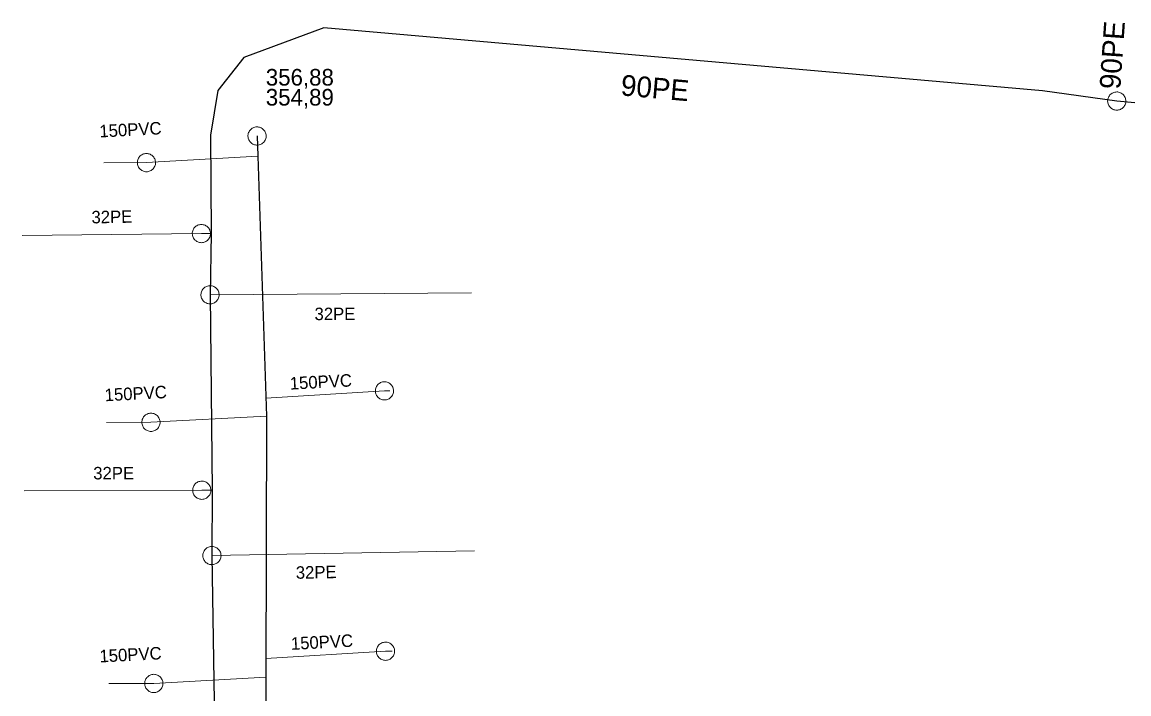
# Model space of a CAD drawing. Extents: x -741806 to -738704, y -1059275 to -1055387.
# Drawn here: x -740777.3 to -740724.1, y -1057612.9 to -1057580.6 of the extents above; entities that cross this region are included whole.
import ezdxf

# ---------------------------------------------------------------- set-up
doc = ezdxf.new("R2010")
doc.units = 0
doc.header["$LTSCALE"] = 0.4
for name, color, linetype, lineweight in [('2', 7, 'Continuous', 25), ('21', 7, 'Continuous', 13), ('3', 7, 'Continuous', 13), ('46', 7, 'Continuous', 13), ('51', 7, 'Continuous', 13), ('52', 7, 'Continuous', 25), ('56', 7, 'Continuous', 13)]:
    doc.layers.add(name, color=color, linetype=linetype, lineweight=lineweight)
for name, color, linetype in [('53', 7, 'Continuous'), ('54', 7, 'Continuous'), ('55', 7, 'Continuous')]:
    doc.layers.add(name, color=color, linetype=linetype)

msp = doc.modelspace()

# ---------------------------------------------------------------- linework, layer by layer
at = {"layer": '2'}
msp.add_lwpolyline([(-740766.015, -1057586.107), (-740765.982, -1057587.074), (-740765.563, -1057599.558), (-740765.594, -1057612.098), (-740765.511, -1057624.514), (-740765.321, -1057634.66)], dxfattribs=at)
at = {"layer": '21'}
for p, q in [((-740768.276, -1057593.736), (-740755.704, -1057593.635)), ((-740768.186, -1057606.262), (-740755.563, -1057606.027))]:
    msp.add_line(p, q, dxfattribs=at)
for points in [[(-740768.221, -1057590.793), (-740768.692, -1057590.797), (-740777.307, -1057590.884)], [(-740768.169, -1057603.12), (-740768.673, -1057603.125), (-740777.206, -1057603.157)]]:
    msp.add_lwpolyline(points, dxfattribs=at)
at = {"layer": '3'}
msp.add_lwpolyline([(-740766, -1057586.544), (-740765.955, -1057586.54), (-740765.911, -1057586.531), (-740765.866, -1057586.518), (-740765.825, -1057586.5), (-740765.784, -1057586.478), (-740765.746, -1057586.452), (-740765.712, -1057586.422), (-740765.68, -1057586.388), (-740765.654, -1057586.352), (-740765.63, -1057586.313), (-740765.61, -1057586.271), (-740765.595, -1057586.228), (-740765.585, -1057586.183), (-740765.579, -1057586.138), (-740765.578, -1057586.092), (-740765.582, -1057586.046), (-740765.591, -1057586.001), (-740765.604, -1057585.958), (-740765.622, -1057585.915), (-740765.645, -1057585.875), (-740765.671, -1057585.838), (-740765.7, -1057585.804), (-740765.734, -1057585.772), (-740765.77, -1057585.744), (-740765.81, -1057585.72), (-740765.851, -1057585.702), (-740765.894, -1057585.686), (-740765.939, -1057585.676), (-740765.985, -1057585.67), (-740766.031, -1057585.67), (-740766.076, -1057585.673), (-740766.12, -1057585.682), (-740766.165, -1057585.695), (-740766.207, -1057585.714), (-740766.247, -1057585.735), (-740766.285, -1057585.761), (-740766.319, -1057585.792), (-740766.351, -1057585.826), (-740766.377, -1057585.862), (-740766.401, -1057585.9), (-740766.421, -1057585.942), (-740766.436, -1057585.986), (-740766.447, -1057586.03), (-740766.452, -1057586.075), (-740766.453, -1057586.121), (-740766.449, -1057586.167), (-740766.441, -1057586.212), (-740766.427, -1057586.255), (-740766.409, -1057586.298), (-740766.386, -1057586.338), (-740766.36, -1057586.375), (-740766.331, -1057586.41), (-740766.297, -1057586.441), (-740766.261, -1057586.469), (-740766.221, -1057586.493), (-740766.18, -1057586.512), (-740766.137, -1057586.527), (-740766.092, -1057586.537), (-740766.046, -1057586.543), (-740766.001, -1057586.544)], dxfattribs=at)
at = {"layer": '46'}
for points in [[(-740770.895, -1057587.383), (-740770.898, -1057587.338), (-740770.905, -1057587.293), (-740770.917, -1057587.248), (-740770.933, -1057587.206), (-740770.955, -1057587.165), (-740770.98, -1057587.126), (-740771.009, -1057587.092), (-740771.041, -1057587.059), (-740771.077, -1057587.031), (-740771.115, -1057587.006), (-740771.156, -1057586.985), (-740771.199, -1057586.968), (-740771.243, -1057586.958), (-740771.288, -1057586.95), (-740771.334, -1057586.948), (-740771.38, -1057586.95), (-740771.425, -1057586.958), (-740771.469, -1057586.97), (-740771.512, -1057586.987), (-740771.553, -1057587.008), (-740771.591, -1057587.033), (-740771.626, -1057587.061), (-740771.659, -1057587.094), (-740771.688, -1057587.13), (-740771.712, -1057587.169), (-740771.732, -1057587.21), (-740771.749, -1057587.252), (-740771.761, -1057587.297), (-740771.768, -1057587.342), (-740771.769, -1057587.388), (-740771.767, -1057587.433), (-740771.76, -1057587.478), (-740771.748, -1057587.523), (-740771.731, -1057587.566), (-740771.71, -1057587.606), (-740771.685, -1057587.645), (-740771.656, -1057587.679), (-740771.623, -1057587.712), (-740771.588, -1057587.74), (-740771.55, -1057587.765), (-740771.509, -1057587.786), (-740771.466, -1057587.803), (-740771.422, -1057587.814), (-740771.377, -1057587.821), (-740771.331, -1057587.823), (-740771.285, -1057587.821), (-740771.24, -1057587.814), (-740771.196, -1057587.801), (-740771.153, -1057587.784), (-740771.112, -1057587.763), (-740771.074, -1057587.738), (-740771.038, -1057587.71), (-740771.006, -1057587.677), (-740770.977, -1057587.641), (-740770.953, -1057587.602), (-740770.932, -1057587.561), (-740770.916, -1057587.519), (-740770.904, -1057587.474), (-740770.897, -1057587.429), (-740770.895, -1057587.384)], [(-740760.329, -1057598.355), (-740760.326, -1057598.4), (-740760.318, -1057598.445), (-740760.306, -1057598.49), (-740760.289, -1057598.532), (-740760.268, -1057598.572), (-740760.243, -1057598.611), (-740760.213, -1057598.646), (-740760.181, -1057598.678), (-740760.144, -1057598.706), (-740760.106, -1057598.73), (-740760.065, -1057598.751), (-740760.022, -1057598.768), (-740759.978, -1057598.778), (-740759.933, -1057598.785), (-740759.886, -1057598.787), (-740759.841, -1057598.784), (-740759.796, -1057598.776), (-740759.752, -1057598.764), (-740759.709, -1057598.747), (-740759.668, -1057598.725), (-740759.63, -1057598.7), (-740759.596, -1057598.672), (-740759.563, -1057598.638), (-740759.535, -1057598.603), (-740759.51, -1057598.564), (-740759.49, -1057598.522), (-740759.474, -1057598.48), (-740759.462, -1057598.435), (-740759.456, -1057598.39), (-740759.455, -1057598.344), (-740759.457, -1057598.299), (-740759.465, -1057598.254), (-740759.477, -1057598.209), (-740759.495, -1057598.166), (-740759.515, -1057598.127), (-740759.54, -1057598.088), (-740759.57, -1057598.053), (-740759.603, -1057598.021), (-740759.639, -1057597.993), (-740759.677, -1057597.969), (-740759.718, -1057597.948), (-740759.761, -1057597.931), (-740759.805, -1057597.92), (-740759.85, -1057597.914), (-740759.897, -1057597.912), (-740759.942, -1057597.915), (-740759.987, -1057597.922), (-740760.031, -1057597.935), (-740760.074, -1057597.952), (-740760.115, -1057597.974), (-740760.153, -1057597.999), (-740760.188, -1057598.027), (-740760.22, -1057598.061), (-740760.248, -1057598.096), (-740760.273, -1057598.135), (-740760.294, -1057598.177), (-740760.309, -1057598.219), (-740760.321, -1057598.264), (-740760.327, -1057598.309), (-740760.329, -1057598.354)], [(-740770.676, -1057599.858), (-740770.679, -1057599.813), (-740770.686, -1057599.768), (-740770.698, -1057599.723), (-740770.714, -1057599.681), (-740770.736, -1057599.64), (-740770.761, -1057599.601), (-740770.79, -1057599.566), (-740770.822, -1057599.533), (-740770.858, -1057599.506), (-740770.896, -1057599.481), (-740770.938, -1057599.46), (-740770.981, -1057599.443), (-740771.025, -1057599.433), (-740771.07, -1057599.425), (-740771.116, -1057599.423), (-740771.162, -1057599.425), (-740771.207, -1057599.433), (-740771.251, -1057599.445), (-740771.294, -1057599.462), (-740771.334, -1057599.483), (-740771.372, -1057599.508), (-740771.407, -1057599.537), (-740771.44, -1057599.57), (-740771.469, -1057599.605), (-740771.494, -1057599.644), (-740771.513, -1057599.685), (-740771.53, -1057599.727), (-740771.542, -1057599.772), (-740771.549, -1057599.817), (-740771.55, -1057599.863), (-740771.548, -1057599.908), (-740771.541, -1057599.953), (-740771.529, -1057599.998), (-740771.512, -1057600.041), (-740771.491, -1057600.081), (-740771.466, -1057600.12), (-740771.437, -1057600.155), (-740771.404, -1057600.188), (-740771.369, -1057600.215), (-740771.331, -1057600.24), (-740771.289, -1057600.261), (-740771.246, -1057600.278), (-740771.202, -1057600.289), (-740771.157, -1057600.296), (-740771.111, -1057600.298), (-740771.065, -1057600.296), (-740771.02, -1057600.289), (-740770.976, -1057600.276), (-740770.933, -1057600.259), (-740770.893, -1057600.238), (-740770.855, -1057600.213), (-740770.819, -1057600.184), (-740770.787, -1057600.151), (-740770.758, -1057600.116), (-740770.733, -1057600.077), (-740770.713, -1057600.036), (-740770.697, -1057599.994), (-740770.685, -1057599.949), (-740770.678, -1057599.904), (-740770.676, -1057599.859)], [(-740760.281, -1057610.862), (-740760.278, -1057610.907), (-740760.271, -1057610.952), (-740760.258, -1057610.997), (-740760.242, -1057611.039), (-740760.22, -1057611.08), (-740760.195, -1057611.118), (-740760.166, -1057611.153), (-740760.133, -1057611.186), (-740760.097, -1057611.213), (-740760.059, -1057611.238), (-740760.018, -1057611.259), (-740759.975, -1057611.275), (-740759.931, -1057611.286), (-740759.885, -1057611.293), (-740759.839, -1057611.295), (-740759.793, -1057611.293), (-740759.749, -1057611.284), (-740759.705, -1057611.273), (-740759.662, -1057611.255), (-740759.621, -1057611.234), (-740759.583, -1057611.209), (-740759.548, -1057611.18), (-740759.516, -1057611.147), (-740759.487, -1057611.112), (-740759.462, -1057611.072), (-740759.443, -1057611.031), (-740759.426, -1057610.989), (-740759.415, -1057610.944), (-740759.408, -1057610.899), (-740759.407, -1057610.853), (-740759.409, -1057610.808), (-740759.416, -1057610.763), (-740759.429, -1057610.718), (-740759.446, -1057610.675), (-740759.467, -1057610.635), (-740759.492, -1057610.597), (-740759.521, -1057610.562), (-740759.555, -1057610.529), (-740759.59, -1057610.502), (-740759.628, -1057610.477), (-740759.669, -1057610.456), (-740759.712, -1057610.44), (-740759.757, -1057610.428), (-740759.802, -1057610.422), (-740759.848, -1057610.42), (-740759.894, -1057610.422), (-740759.939, -1057610.43), (-740759.982, -1057610.442), (-740760.025, -1057610.46), (-740760.066, -1057610.481), (-740760.104, -1057610.506), (-740760.14, -1057610.535), (-740760.171, -1057610.568), (-740760.2, -1057610.603), (-740760.225, -1057610.643), (-740760.245, -1057610.684), (-740760.261, -1057610.726), (-740760.272, -1057610.771), (-740760.279, -1057610.816), (-740760.281, -1057610.861)], [(-740770.542, -1057612.402), (-740770.545, -1057612.357), (-740770.552, -1057612.312), (-740770.564, -1057612.268), (-740770.58, -1057612.226), (-740770.601, -1057612.185), (-740770.626, -1057612.146), (-740770.656, -1057612.111), (-740770.688, -1057612.078), (-740770.724, -1057612.05), (-740770.762, -1057612.025), (-740770.803, -1057612.004), (-740770.846, -1057611.988), (-740770.89, -1057611.977), (-740770.935, -1057611.969), (-740770.981, -1057611.967), (-740771.027, -1057611.969), (-740771.072, -1057611.977), (-740771.116, -1057611.988), (-740771.159, -1057612.006), (-740771.2, -1057612.027), (-740771.238, -1057612.052), (-740771.273, -1057612.08), (-740771.306, -1057612.113), (-740771.334, -1057612.148), (-740771.359, -1057612.187), (-740771.379, -1057612.228), (-740771.396, -1057612.27), (-740771.408, -1057612.316), (-740771.415, -1057612.361), (-740771.416, -1057612.407), (-740771.414, -1057612.452), (-740771.407, -1057612.497), (-740771.395, -1057612.541), (-740771.378, -1057612.584), (-740771.358, -1057612.624), (-740771.333, -1057612.663), (-740771.303, -1057612.698), (-740771.27, -1057612.731), (-740771.235, -1057612.759), (-740771.197, -1057612.784), (-740771.156, -1057612.805), (-740771.113, -1057612.821), (-740771.069, -1057612.833), (-740771.024, -1057612.84), (-740770.978, -1057612.842), (-740770.932, -1057612.84), (-740770.887, -1057612.833), (-740770.843, -1057612.821), (-740770.8, -1057612.803), (-740770.759, -1057612.782), (-740770.721, -1057612.757), (-740770.685, -1057612.729), (-740770.653, -1057612.696), (-740770.625, -1057612.661), (-740770.6, -1057612.622), (-740770.579, -1057612.581), (-740770.563, -1057612.539), (-740770.551, -1057612.493), (-740770.544, -1057612.448), (-740770.542, -1057612.403)]]:
    msp.add_lwpolyline(points, dxfattribs=at)
at = {"layer": '51'}
for points in [[(-740725.127, -1057584.384), (-740725.13, -1057584.429), (-740725.127, -1057584.475), (-740725.12, -1057584.521), (-740725.108, -1057584.564), (-740725.092, -1057584.607), (-740725.071, -1057584.648), (-740725.046, -1057584.686), (-740725.017, -1057584.722), (-740724.984, -1057584.754), (-740724.949, -1057584.783), (-740724.91, -1057584.808), (-740724.869, -1057584.829), (-740724.827, -1057584.845), (-740724.783, -1057584.857), (-740724.737, -1057584.864), (-740724.691, -1057584.866), (-740724.646, -1057584.864), (-740724.601, -1057584.857), (-740724.556, -1057584.844), (-740724.513, -1057584.827), (-740724.473, -1057584.806), (-740724.434, -1057584.782), (-740724.399, -1057584.753), (-740724.367, -1057584.721), (-740724.338, -1057584.685), (-740724.313, -1057584.646), (-740724.292, -1057584.606), (-740724.276, -1057584.562), (-740724.264, -1057584.518), (-740724.257, -1057584.473), (-740724.255, -1057584.428), (-740724.257, -1057584.382), (-740724.265, -1057584.336), (-740724.276, -1057584.293), (-740724.293, -1057584.25), (-740724.314, -1057584.209), (-740724.339, -1057584.171), (-740724.368, -1057584.135), (-740724.401, -1057584.103), (-740724.436, -1057584.074), (-740724.474, -1057584.049), (-740724.515, -1057584.028), (-740724.558, -1057584.013), (-740724.602, -1057584), (-740724.648, -1057583.993), (-740724.694, -1057583.991), (-740724.739, -1057583.994), (-740724.784, -1057584), (-740724.829, -1057584.013), (-740724.871, -1057584.03), (-740724.912, -1057584.051), (-740724.951, -1057584.075), (-740724.986, -1057584.104), (-740725.018, -1057584.136), (-740725.047, -1057584.172), (-740725.072, -1057584.211), (-740725.092, -1057584.251), (-740725.109, -1057584.295), (-740725.12, -1057584.339), (-740725.127, -1057584.383)], [(-740769.128, -1057590.799), (-740769.126, -1057590.844), (-740769.119, -1057590.889), (-740769.106, -1057590.934), (-740769.09, -1057590.976), (-740769.069, -1057591.017), (-740769.044, -1057591.056), (-740769.014, -1057591.09), (-740768.982, -1057591.123), (-740768.946, -1057591.151), (-740768.908, -1057591.176), (-740768.866, -1057591.196), (-740768.823, -1057591.213), (-740768.779, -1057591.225), (-740768.734, -1057591.231), (-740768.688, -1057591.233), (-740768.642, -1057591.231), (-740768.597, -1057591.223), (-740768.553, -1057591.211), (-740768.51, -1057591.194), (-740768.47, -1057591.172), (-740768.432, -1057591.147), (-740768.396, -1057591.119), (-740768.364, -1057591.086), (-740768.336, -1057591.05), (-740768.311, -1057591.011), (-740768.29, -1057590.97), (-740768.274, -1057590.928), (-740768.263, -1057590.883), (-740768.256, -1057590.838), (-740768.254, -1057590.792), (-740768.257, -1057590.747), (-740768.264, -1057590.702), (-740768.277, -1057590.657), (-740768.293, -1057590.615), (-740768.314, -1057590.574), (-740768.339, -1057590.535), (-740768.369, -1057590.501), (-740768.401, -1057590.468), (-740768.437, -1057590.44), (-740768.475, -1057590.415), (-740768.517, -1057590.395), (-740768.56, -1057590.378), (-740768.604, -1057590.367), (-740768.649, -1057590.36), (-740768.695, -1057590.358), (-740768.741, -1057590.36), (-740768.786, -1057590.369), (-740768.83, -1057590.38), (-740768.873, -1057590.397), (-740768.913, -1057590.419), (-740768.951, -1057590.444), (-740768.987, -1057590.472), (-740769.019, -1057590.505), (-740769.047, -1057590.541), (-740769.072, -1057590.58), (-740769.093, -1057590.621), (-740769.109, -1057590.663), (-740769.12, -1057590.708), (-740769.127, -1057590.753), (-740769.128, -1057590.798)], [(-740768.711, -1057593.77), (-740768.706, -1057593.814), (-740768.695, -1057593.859), (-740768.679, -1057593.903), (-740768.66, -1057593.943), (-740768.636, -1057593.982), (-740768.608, -1057594.019), (-740768.576, -1057594.052), (-740768.542, -1057594.082), (-740768.504, -1057594.107), (-740768.464, -1057594.129), (-740768.421, -1057594.147), (-740768.377, -1057594.16), (-740768.332, -1057594.169), (-740768.287, -1057594.172), (-740768.241, -1057594.171), (-740768.195, -1057594.165), (-740768.151, -1057594.154), (-740768.108, -1057594.139), (-740768.066, -1057594.119), (-740768.027, -1057594.094), (-740767.991, -1057594.066), (-740767.958, -1057594.036), (-740767.928, -1057594), (-740767.902, -1057593.963), (-740767.88, -1057593.922), (-740767.863, -1057593.88), (-740767.85, -1057593.837), (-740767.842, -1057593.791), (-740767.838, -1057593.745), (-740767.839, -1057593.699), (-740767.846, -1057593.655), (-740767.856, -1057593.61), (-740767.872, -1057593.566), (-740767.891, -1057593.526), (-740767.915, -1057593.487), (-740767.943, -1057593.45), (-740767.975, -1057593.417), (-740768.009, -1057593.387), (-740768.047, -1057593.362), (-740768.087, -1057593.34), (-740768.13, -1057593.322), (-740768.174, -1057593.309), (-740768.219, -1057593.301), (-740768.264, -1057593.297), (-740768.31, -1057593.298), (-740768.356, -1057593.304), (-740768.4, -1057593.316), (-740768.443, -1057593.33), (-740768.485, -1057593.35), (-740768.524, -1057593.375), (-740768.56, -1057593.403), (-740768.594, -1057593.433), (-740768.623, -1057593.469), (-740768.649, -1057593.506), (-740768.671, -1057593.547), (-740768.688, -1057593.589), (-740768.701, -1057593.633), (-740768.709, -1057593.678), (-740768.713, -1057593.724), (-740768.711, -1057593.769)], [(-740769.109, -1057603.129), (-740769.107, -1057603.174), (-740769.099, -1057603.219), (-740769.087, -1057603.264), (-740769.07, -1057603.306), (-740769.049, -1057603.346), (-740769.024, -1057603.385), (-740768.994, -1057603.42), (-740768.962, -1057603.452), (-740768.925, -1057603.48), (-740768.887, -1057603.504), (-740768.846, -1057603.525), (-740768.803, -1057603.542), (-740768.759, -1057603.553), (-740768.713, -1057603.56), (-740768.667, -1057603.561), (-740768.621, -1057603.558), (-740768.577, -1057603.551), (-740768.533, -1057603.538), (-740768.49, -1057603.521), (-740768.449, -1057603.499), (-740768.411, -1057603.474), (-740768.376, -1057603.446), (-740768.344, -1057603.412), (-740768.316, -1057603.377), (-740768.291, -1057603.338), (-740768.27, -1057603.296), (-740768.255, -1057603.254), (-740768.243, -1057603.209), (-740768.237, -1057603.164), (-740768.235, -1057603.118), (-740768.238, -1057603.073), (-740768.246, -1057603.028), (-740768.258, -1057602.983), (-740768.275, -1057602.941), (-740768.296, -1057602.901), (-740768.322, -1057602.862), (-740768.351, -1057602.827), (-740768.383, -1057602.795), (-740768.42, -1057602.767), (-740768.458, -1057602.743), (-740768.499, -1057602.722), (-740768.542, -1057602.705), (-740768.586, -1057602.695), (-740768.632, -1057602.687), (-740768.678, -1057602.686), (-740768.724, -1057602.689), (-740768.768, -1057602.697), (-740768.812, -1057602.709), (-740768.855, -1057602.726), (-740768.896, -1057602.748), (-740768.934, -1057602.773), (-740768.969, -1057602.801), (-740769.001, -1057602.835), (-740769.029, -1057602.87), (-740769.054, -1057602.909), (-740769.075, -1057602.951), (-740769.09, -1057602.993), (-740769.102, -1057603.038), (-740769.108, -1057603.083), (-740769.109, -1057603.128)], [(-740768.618, -1057606.197), (-740768.622, -1057606.242), (-740768.622, -1057606.288), (-740768.617, -1057606.334), (-740768.607, -1057606.378), (-740768.592, -1057606.421), (-740768.573, -1057606.464), (-740768.549, -1057606.503), (-740768.523, -1057606.54), (-740768.491, -1057606.573), (-740768.457, -1057606.603), (-740768.42, -1057606.63), (-740768.38, -1057606.653), (-740768.338, -1057606.671), (-740768.294, -1057606.685), (-740768.249, -1057606.693), (-740768.203, -1057606.698), (-740768.158, -1057606.698), (-740768.112, -1057606.692), (-740768.067, -1057606.682), (-740768.024, -1057606.667), (-740767.983, -1057606.648), (-740767.943, -1057606.625), (-740767.906, -1057606.597), (-740767.873, -1057606.567), (-740767.842, -1057606.532), (-740767.815, -1057606.494), (-740767.794, -1057606.455), (-740767.775, -1057606.412), (-740767.762, -1057606.369), (-740767.752, -1057606.324), (-740767.748, -1057606.279), (-740767.749, -1057606.233), (-740767.754, -1057606.187), (-740767.764, -1057606.143), (-740767.779, -1057606.1), (-740767.798, -1057606.057), (-740767.821, -1057606.018), (-740767.848, -1057605.981), (-740767.88, -1057605.948), (-740767.914, -1057605.918), (-740767.951, -1057605.891), (-740767.991, -1057605.868), (-740768.033, -1057605.851), (-740768.076, -1057605.836), (-740768.122, -1057605.828), (-740768.167, -1057605.823), (-740768.213, -1057605.824), (-740768.258, -1057605.829), (-740768.303, -1057605.839), (-740768.347, -1057605.854), (-740768.388, -1057605.873), (-740768.428, -1057605.896), (-740768.464, -1057605.924), (-740768.498, -1057605.954), (-740768.528, -1057605.989), (-740768.555, -1057606.027), (-740768.577, -1057606.066), (-740768.596, -1057606.109), (-740768.609, -1057606.152), (-740768.618, -1057606.196)]]:
    msp.add_lwpolyline(points, dxfattribs=at)
at = {"layer": '52'}
msp.add_lwpolyline([(-740723.829, -1057584.519), (-740724.693, -1057584.43), (-740728.257, -1057583.93), (-740762.811, -1057580.919), (-740766.647, -1057582.333), (-740767.896, -1057583.914), (-740768.258, -1057586.068), (-740768.221, -1057590.793), (-740768.276, -1057593.736), (-740768.169, -1057603.12), (-740768.186, -1057606.262), (-740768.039, -1057615.274), (-740767.925, -1057618.713), (-740767.909, -1057629.21), (-740767.824, -1057631.212), (-740767.817, -1057641.745), (-740767.701, -1057643.739), (-740767.68, -1057653.215)], dxfattribs=at)
at = {"layer": '56'}
for points in [[(-740773.373, -1057587.395), (-740771.333, -1057587.386), (-740765.982, -1057587.074)], [(-740759.631, -1057598.347), (-740759.892, -1057598.35), (-740765.592, -1057598.695)], [(-740773.247, -1057599.872), (-740771.114, -1057599.861), (-740765.563, -1057599.558)], [(-740759.524, -1057610.855), (-740759.844, -1057610.858), (-740765.592, -1057611.203)], [(-740773.139, -1057612.412), (-740770.98, -1057612.405), (-740765.594, -1057612.098)]]:
    msp.add_lwpolyline(points, dxfattribs=at)

# ---------------------------------------------------------------- texts
at = {"layer": '53'}
for rotation, p in [(86, (-740724.525, -1057583.887)), (355, (-740748.56, -1057584.153))]:
    msp.add_text('90PE', height=1, rotation=rotation, dxfattribs=at).set_placement(p)
at = {"layer": '54'}
for p in [(-740773.969, -1057590.307), (-740764.148, -1057607.379)]:
    msp.add_text('32PE', height=0.6, rotation=1, dxfattribs=at).set_placement(p)
for p in [(-740763.253, -1057594.953), (-740773.889, -1057602.602)]:
    msp.add_text('32PE', height=0.6, dxfattribs=at).set_placement(p)
at = {"layer": '55'}
for s, p in [('356,88', (-740765.595, -1057583.685)), ('354,89', (-740765.595, -1057584.645))]:
    msp.add_text(s, height=0.8, dxfattribs=at).set_placement(p)
for p in [(-740773.578, -1057586.179), (-740764.427, -1057598.293), (-740773.324, -1057598.852), (-740764.373, -1057610.795), (-740773.574, -1057611.398)]:
    msp.add_text('150PVC', height=0.6, rotation=3, dxfattribs=at).set_placement(p)

doc.saveas('drawing.dxf')
